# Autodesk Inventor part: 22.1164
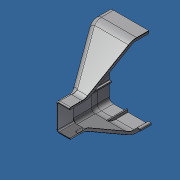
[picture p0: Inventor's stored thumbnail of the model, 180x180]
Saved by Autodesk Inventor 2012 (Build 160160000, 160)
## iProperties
Created: 2018-02
Part Number: 22.1164
Material: ABS Plastic
Document SubType Name: Modeling
Designer: Admin
Density: 1.06 g/cm^3
Mass: 84.3332 g
Surface Area: 651.59 cm^2
Volume: 79.5596 cm^3
Description: COVER FOR FOOT 45
Stock Number: 22.1164 HALF COVER FOR FOOT 45
Translation Standard: STEP AP214IS
FileName: 22_1164_0_2.stp
PreProcessor: ACIS
PostProcessor: Build: 160, Release: 2012 RTM - Date: Tue 03/01/2011
Sent Units: inch
Uncertainty: 1e-06
Author: Admin
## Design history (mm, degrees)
feature "Base1"
sketch "Sketch1"
  geometry: L1 (19, 30.665)-(19, 31.656) reference; L2 (4.994, 28.665)-(18, 28.665) reference; L3 (0, 0)-(0, 29.643) reference; L4 (19.5, 0)-(0, 0) reference; L5 (19.5, 0)-(19.5, 0.5) reference; L6 (19.5, 0.5)-(20, 0.5) reference; L7 (20, 0.5)-(20, 31.656) reference; L8 (19, 31.656)-(20, 31.656) reference; L9 (19.25, 15)-(19.25, 25) reference; L10 (15.9, 15)-(19.25, 15) reference; L11 (15.9, 25)-(15.9, 15) reference; L12 (19.25, 25)-(15.9, 25) reference; 3 further points; 2 other entities
  constraints: 2 other
extrude "Extrusion1" join sketch "Sketch1" distance "d0" = 0.5; taper "d1" = 0 deg
sketch "Sketch4"
  geometry: L1 (20, -31.656)-(20, -0.5) reference; L2 (17.5, -28.531)-(3.861, -28.531) reference; L3 (19.25, -25)-(15.9, -25) reference; L4 (15.9, -25)-(15.9, -15) reference; L5 (15.9, -15)-(19.25, -15) reference; L6 (19.25, -15)-(19.25, -25) reference; L7 (0, 0)-(20, 0); L8 (20, 0)-(20, -28.531); L9 (20, -28.531)-(0, -28.531); L10 (0, -28.531)-(0, 0); 1 further point
  constraints: 8 end point, 2 collinear, 2 parallel, 1 horizontal, 1 perpendicular
extrude "Extrusion2" join sketch "Sketch4" distance "d2" = 0.5; taper "d3" = 0 deg
node "1"
